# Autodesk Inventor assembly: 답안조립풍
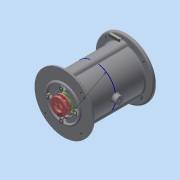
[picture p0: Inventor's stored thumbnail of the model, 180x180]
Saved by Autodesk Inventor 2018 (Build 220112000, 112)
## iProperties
Created: 2024-10
Part Number: 답안조립풍
Material: 일반
Document SubType Name: Assembly
Designer: home
Author: home
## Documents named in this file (6)
- C:\Users\home\Desktop\741004V1007\답안조립풍.iam
- C:\Users\home\Desktop\741004V1007\본체1.ipt
- C:\Users\home\Desktop\741004V1007\스러스트 볼베어링 512 02.ipt
- C:\Users\home\Desktop\741004V1007\어뎁터.ipt
- C:\Users\home\Desktop\741004V1007\육각 소켓 머리 볼트 M5x10.ipt
- C:\Users\home\Desktop\741004V1007\평행키 5x5x22.ipt
